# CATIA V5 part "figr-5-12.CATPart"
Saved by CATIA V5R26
Part number: Part1
Bounding box of the stored display mesh (mm): x 0 to 150, y -70 to 70, z -150 to 69.804
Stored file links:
  D:\_Deepak\CATIA\CATIA V5-6R2016_Deepak\Resources\Part files\Partfiles\c05_catia_v5_6r2016_prt\figr-5-12.CATPart
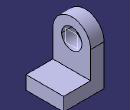
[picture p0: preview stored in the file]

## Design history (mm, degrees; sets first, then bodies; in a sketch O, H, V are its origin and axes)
Set1
  Plane1: type 1Curve, Element1 edge [face of Pad1 | face of Pad1]
Body1 (main body)
  Sketch1 on yz-plane, origin (0, 0, 0), H (0, 1, 0), V (0, 0, 1)
    arc A1 centre (0, 0) radius 70 from (70, 0) to (-70, 0) ccw
    point P1 (70, 0)
    point P2 (-70, 0)
    line L1 (-70, 0) -> (-70, -150)
    line L2 (-70, -150) -> (70, -150)
    line L3 (70, -150) -> (70, 0)
    circle A2 centre (0, 0) radius 37.5
    radius A1 = 70
    radius A2 = 37.5
    distance O L2 = 150
    coincidence: P1 H, P2 H
    tangency: L1 A1, L3 A1
    horizontal: L2 H
  Pad1: profile Sketch1, direction (1, 0, 0), length 50
  Sketch2 on face of Pad1, origin (50, 0, 0), H (0, 1, 0), V (0, 0, 1)
    line L1 (-70, -150) -> (70, -150)
    line L2 (70, -150) -> (70, -100)
    line L3 (70, -100) -> (-70, -100)
    line L4 (-70, -100) -> (-70, -150)
    reference projected line E1 (-70, -150) -> (70, -150) from edge [face of Pad1 | face of Pad1]
    reference projected line E2 (-70, 0) -> (-70, -150) from edge [face of Pad1 | face of Pad1]
    reference projected line E3 (70, -150) -> (70, 0) from edge [face of Pad1 | face of Pad1]
    length L2 = 50
    horizontal: L1 H, L3 H
    vertical: L2 V, L4 V
    coincidence: L1 E1, E2 L4, L2 E3
  Pad2: profile Sketch2, direction (1, 0, 0), length 100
